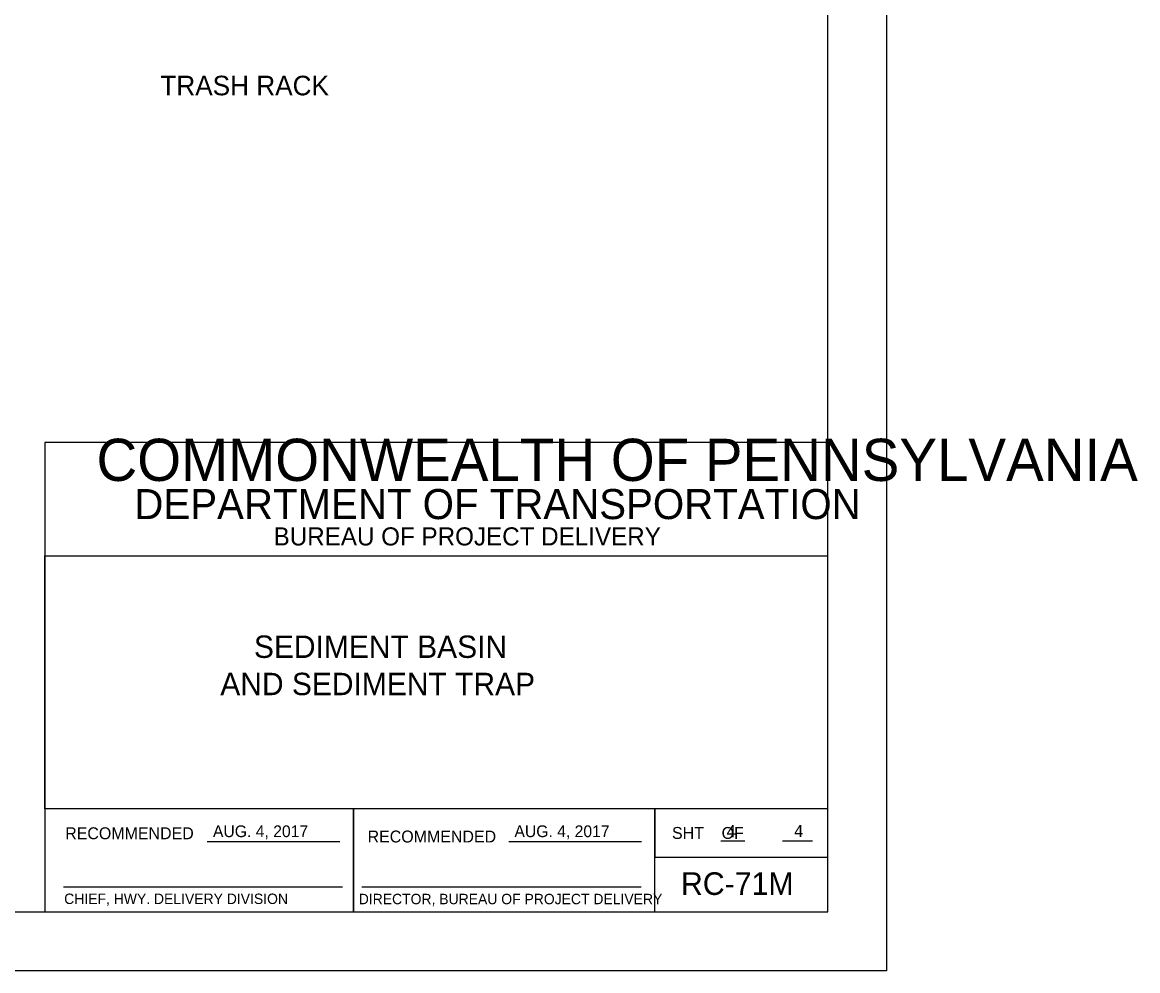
# Model space of a CAD drawing. Extents: x 636462 to 639890, y 299944 to 300538.
# Drawn here: x 639605.1 to 639890, y 299944.4 to 300186.8 of the extents above; entities that cross this region are included whole.
import ezdxf

# ---------------------------------------------------------------- set-up
doc = ezdxf.new("R2010")
doc.units = 0
for name, color, linetype in [('1', 7, 'Continuous'), ('Default', 7, 'Continuous'), ('PLT-BNDY', 7, 'Continuous')]:
    doc.layers.add(name, color=color, linetype=linetype)

msp = doc.modelspace()

# ---------------------------------------------------------------- linework, layer by layer
at = {"layer": '1'}
for p, q in [((639652.38, 299977.44), (639686.27, 299977.44)), ((639729.38, 299977.44), (639763.25, 299977.44)), ((639783.54, 299977.66), (639789.68, 299977.66)), ((639799.35, 299977.66), (639806.99, 299977.66)), ((639615.68, 299965.87), (639686.93, 299965.87)), ((639691.85, 299965.87), (639763.19, 299965.87))]:
    msp.add_line(p, q, dxfattribs=at)
msp.add_lwpolyline([(639810.91, 299959.45), (639810.91, 300523.45), (639024.91, 300523.45), (639024.91, 299959.45), (639810.91, 299959.45), (639810.91, 299985.81), (639610.91, 299985.81), (639610.91, 300050.49), (639810.91, 300050.49), (639810.91, 300079.45), (639610.91, 300079.45), (639610.91, 299959.45), (639689.72, 299959.45), (639689.72, 299985.81), (639689.72, 299959.45), (639766.72, 299959.45), (639766.72, 299985.81), (639766.72, 299973.49), (639810.91, 299973.49)], dxfattribs=at)
at = {"layer": 'PLT-BNDY'}
msp.add_lwpolyline([(638984.91, 300538.45), (639825.91, 300538.45), (639825.91, 299944.45), (638984.91, 299944.45)], close=True, dxfattribs=at)

# ---------------------------------------------------------------- texts
at = {"layer": '1'}
for s, height, p in [('COMMONWEALTH OF PENNSYLVANIA', 10.7834, (639624.07, 300069.59)), ('DEPARTMENT OF TRANSPORTATION', 7.6843, (639633.75, 300059.84)), ('BUREAU OF PROJECT DELIVERY', 4.6221, (639669.32, 300053.11)), ('RECOMMENDED', 3.048, (639616.08, 299978.04)), ('AUG. 4, 2017', 3, (639653.83, 299978.58)), ('RECOMMENDED', 3.048, (639693.32, 299977.21)), ('AUG. 4, 2017', 3, (639730.83, 299978.58)), ('SHT    OF', 3.048, (639771.08, 299978.12)), ('4', 3.13, (639785.05, 299978.54)), ('4', 3.13, (639802.28, 299978.59)), ('APPROVED', 0.0192, (639653.94, 299977.38)), ('APPROVED', 0.0192, (639653.94, 299977.38)), ('APPROVED', 0.0192, (639653.94, 299977.38)), ('APPROVED', 0.0192, (639653.94, 299977.38)), ('CHIEF, HWY. DELIVERY DIVISION', 2.6623, (639615.82, 299961.49)), ('DIRECTOR, BUREAU OF PROJECT DELIVERY', 2.6623, (639691.07, 299961.43))]:
    msp.add_text(s, height=height, dxfattribs=at).set_placement(p)
at = {"layer": 'Default'}
for s, height, p in [('TRASH RACK', 4.997, (639640.39, 300168.13)), ('SEDIMENT BASIN', 5.7257, (639664.29, 300024.37)), ('AND SEDIMENT TRAP', 5.7257, (639655.7, 300014.85)), ('RC-71M', 5.779, (639773.37, 299963.81))]:
    msp.add_text(s, height=height, dxfattribs=at).set_placement(p)

doc.saveas('drawing.dxf')
